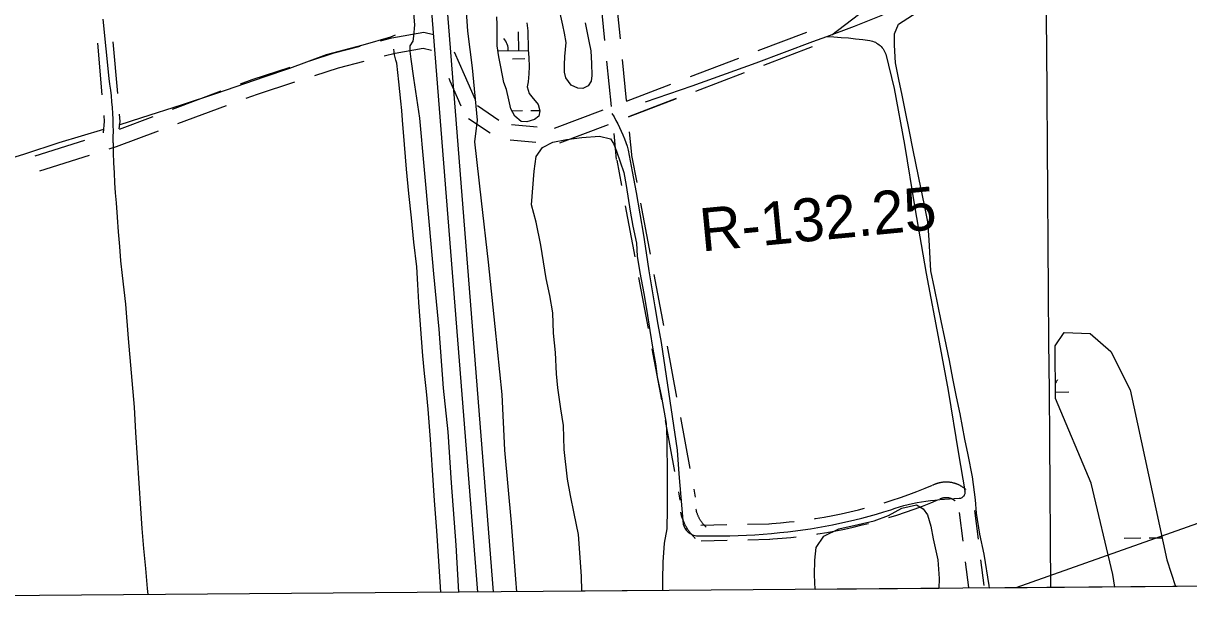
# Model space of a CAD drawing. Extents: x 3540316 to 3578335, y 553172 to 578787.
# Drawn here: x 3547815 to 3550058, y 558573 to 559700 of the extents above; entities that cross this region are included whole.
import ezdxf

# ---------------------------------------------------------------- set-up
doc = ezdxf.new("R2010")
doc.units = 0
for name, color, linetype in [('V-DTCH-CNTR', 7, 'Continuous'), ('V-GRID-FRAM', 7, 'Continuous'), ('V-GRID-MAJR', 7, 'Continuous'), ('V-LEVE-TOET', 7, 'Continuous'), ('V-RIVR-RANG-IDEN', 7, 'Continuous'), ('V-ROAD-CNTR', 7, 'Continuous'), ('V-SITE-VEGE', 7, 'Continuous'), ('V-SURV-LINE', 7, 'Continuous'), ('V-TOPO-BNDY', 7, 'Continuous'), ('V-TOPO-SHOR', 7, 'Continuous'), ('V-WETL-SWMP', 7, 'Continuous')]:
    doc.layers.add(name, color=color, linetype=linetype)

msp = doc.modelspace()

# ---------------------------------------------------------------- linework, layer by layer
at = {"layer": 'V-DTCH-CNTR'}
for points in [[(3547987.7, 559470.4), (3547988, 559481.7), (3547988.1, 559493), (3547988, 559504.3), (3547987.7, 559515.6), (3547987.2, 559526.9), (3547986.5, 559538.2), (3547985.5, 559549.5), (3547984.4, 559560.8), (3547983.1, 559572), (3547981.5, 559583.3), (3547979.8, 559594.4), (3547974.1, 559651.3), (3547968.6, 559708.2)], [(3549012.5, 559549), (3549102.4, 559580.2), (3549225.7, 559624.1), (3549334.7, 559665.2), (3549361.7, 559675.1), (3549415.1, 559694.7), (3549466.2, 559715.4), (3549485, 559724.9)], [(3549361.7, 559675.1), (3549375.5, 559674.4), (3549389.4, 559673.4), (3549403.2, 559672.2), (3549417, 559670.8), (3549430.7, 559669.2), (3549444.5, 559667.4), (3549447.2, 559666.8), (3549449.9, 559666), (3549452.6, 559665), (3549455.2, 559663.9), (3549457.6, 559662.5), (3549460, 559661), (3549462.3, 559659.3), (3549464.4, 559657.5), (3549466.4, 559655.5), (3549468.3, 559653.4), (3549470, 559651.2), (3549471.5, 559648.8), (3549472.8, 559646.3), (3549474, 559643.8), (3549475, 559641.1), (3549491.6, 559575.2), (3549511, 559467.1), (3549530.9, 559345.4), (3549552.8, 559218.8), (3549577.7, 559086.3), (3549595, 558993.4), (3549615.5, 558871.2), (3549627.7, 558800.2)], [(3548618.6, 558604.9), (3548614.8, 558664.5), (3548610.7, 558723.1), (3548606.6, 558781.7), (3548602.5, 558840.3), (3548598.4, 558898.9), (3548594.4, 558957.5), (3548590.7, 558991.7), (3548587.3, 559026), (3548584.2, 559060.2), (3548581.3, 559094.5), (3548578.6, 559128.8), (3548576.2, 559163.1), (3548574, 559197.4), (3548572.1, 559231.7), (3548566.9, 559278.8), (3548562, 559325.8), (3548557.3, 559372.8), (3548552.8, 559419.9), (3548548.6, 559467), (3548544.7, 559514.1), (3548543.3, 559532.5), (3548541.6, 559550.8), (3548539.9, 559569.2), (3548538, 559587.5), (3548536, 559605.8), (3548533.8, 559624), (3548532.2, 559629.2), (3548530.8, 559634.5), (3548529.7, 559639.9), (3548528.8, 559645.3), (3548528.1, 559650.7)], [(3548948.1, 559526.9), (3548952, 559520.2), (3548955.8, 559513.4), (3548959.4, 559506.6), (3548962.8, 559499.6), (3548966, 559492.6), (3548969.1, 559485.4), (3548971.9, 559478.2), (3548974.6, 559471), (3548977.1, 559463.6), (3548979.4, 559456.2), (3548987.2, 559415.4), (3548994.7, 559374.6), (3549001.9, 559333.7), (3549008.8, 559292.7), (3549013.9, 559258.2), (3549019.3, 559223.6), (3549024.8, 559189.1), (3549030.5, 559154.6), (3549036.4, 559120.2), (3549042.5, 559085.8), (3549073.3, 558878.3), (3549076.9, 558833.2), (3549080.7, 558788.1), (3549084.5, 558743), (3549084.6, 558740.5), (3549084.9, 558738), (3549085.4, 558735.5), (3549086.1, 558733.1), (3549087.1, 558730.8), (3549088.2, 558728.5), (3549089.6, 558726.4), (3549091.1, 558724.4), (3549092.8, 558722.5), (3549094.6, 558720.8), (3549096.6, 558719.2), (3549098.7, 558717.8), (3549100.9, 558716.6), (3549103.2, 558715.6), (3549105.6, 558714.8), (3549108.1, 558714.3), (3549110.6, 558713.9), (3549126.6, 558713.5), (3549142.7, 558713.4), (3549158.8, 558713.4), (3549174.8, 558713.7), (3549190.9, 558714.2), (3549206.9, 558714.9), (3549223, 558715.8), (3549239, 558716.9), (3549255, 558718.2), (3549271, 558719.7), (3549286.9, 558721.5), (3549301.3, 558723.2), (3549315.7, 558725.1), (3549330, 558727.3), (3549344.3, 558729.6), (3549358.6, 558732.1), (3549372.8, 558734.9), (3549387, 558737.8), (3549401.2, 558740.9), (3549415.3, 558744.3), (3549429.4, 558747.8), (3549443.4, 558751.5), (3549457.3, 558755.5), (3549471.2, 558759.6), (3549485, 558763.9), (3549493.3, 558766.7), (3549501.6, 558769.4), (3549509.9, 558771.8), (3549518.4, 558773.9), (3549526.9, 558775.9), (3549535.4, 558777.6), (3549544, 558779.1), (3549552.6, 558780.3), (3549561.3, 558781.3), (3549569.9, 558782.1), (3549579.2, 558783.3), (3549588.4, 558784.3), (3549597.7, 558785), (3549607, 558785.5), (3549616.3, 558785.8), (3549618, 558785.9), (3549619.5, 558786.3), (3549621.1, 558786.8), (3549622.5, 558787.6), (3549623.8, 558788.6), (3549625, 558789.7), (3549626, 558790.9), (3549626.8, 558792.3), (3549627.4, 558793.8), (3549627.8, 558795.4)], [(3547987.7, 559470.4), (3547988, 559451.1), (3547988.6, 559431.8), (3547989.5, 559412.6), (3547990.6, 559393.4), (3547991.9, 559374.1), (3547993.6, 559354.9), (3547995.4, 559326.9), (3547997.4, 559298.9), (3547999.7, 559271), (3548002.2, 559243), (3548005, 559215.1), (3548008.1, 559187.2), (3548011.4, 559159.4), (3548016.9, 559093.4), (3548022.4, 559027.4), (3548028, 558961.4), (3548030.7, 558912.6), (3548033.7, 558863.8), (3548036.9, 558815), (3548040.3, 558766.2), (3548043.2, 558727.6), (3548046.3, 558689), (3548049.7, 558650.4), (3548053.4, 558611.9), (3548054.5, 558600.5)], [(3549627.8, 558795.4), (3549628, 558797), (3549628, 558798.6), (3549627.7, 558800.2)]]:
    msp.add_lwpolyline(points, dxfattribs=at)
at = {"layer": 'V-GRID-FRAM'}
msp.add_lwpolyline([(3544387.2, 576756), (3576013, 576999.8), (3576161.1, 558817.2), (3544519.4, 558573.3), (3544387.2, 576756)], dxfattribs=at)
at = {"layer": 'V-GRID-MAJR'}
msp.add_spline([(3549793, 558613.9), (3549748.1, 564672.9), (3549703.1, 570733.8), (3549658.2, 576794.8), (3549658.2, 576796.7)], degree=3, dxfattribs=at)
at = {"layer": 'V-LEVE-TOET'}
for points in [[(3548689, 559513.8), (3548679.3, 559614.7), (3548670.6, 559685.6), (3548663.6, 559790.1), (3548654.6, 559906.5), (3548645.6, 560011.5), (3548639.8, 560118), (3548630.7, 560243.8), (3548621.2, 560361.3), (3548614.5, 560479.6), (3548602.8, 560594.3), (3548594.9, 560713.8), (3548584.4, 560819.2), (3548574.1, 560944.1), (3548567.4, 561062), (3548559.4, 561201.1), (3548555.6, 561289.3), (3548543.2, 561437.7), (3548530.1, 561572.4), (3548518.7, 561693.5), (3548505.7, 561814.5)], [(3548562.3, 559765.9), (3548568.2, 559697.8), (3548566, 559675.4), (3548564.5, 559666), (3548559.1, 559656.9)], [(3548559.1, 559656.9), (3548559.2, 559646.8), (3548560.9, 559631.5), (3548566.2, 559595.1), (3548577.3, 559517.6), (3548585.8, 559425.1), (3548596.4, 559311.9), (3548604.5, 559217.9), (3548614.6, 559111.4), (3548623.3, 558997.8), (3548632.1, 558914), (3548638.2, 558815.7), (3548647.3, 558695.4), (3548652.8, 558605.1)], [(3548765.1, 558606), (3548763, 558630.4), (3548754.4, 558738.9), (3548742.1, 558878.7), (3548736.6, 558985.7), (3548723.5, 559116.5), (3548710.1, 559240.2), (3548696.8, 559358.5), (3548683.8, 559472), (3548689, 559513.8)]]:
    msp.add_lwpolyline(points, dxfattribs=at)
at = {"layer": 'V-ROAD-CNTR'}
for points in [[(3548934.3, 559667.4), (3548924.5, 559766.9)], [(3548964.2, 559670.4), (3548954.4, 559769.9)], [(3549371.5, 559678.1), (3549422.8, 559717.5), (3549451.2, 559737.4)], [(3548502.2, 559666.6), (3548524.4, 559672.4), (3548585.7, 559683.2), (3548604.6, 559678.7)], [(3549229.7, 559647.8), (3549323.1, 559683.5)], [(3547966.8, 559562.6), (3547958, 559662.2)], [(3547996.7, 559565.2), (3547987.9, 559664.8)], [(3548366.6, 559628.4), (3548413.1, 559643.5), (3548463.5, 559656.6)], [(3548509.7, 559637.6), (3548530.8, 559643), (3548584.8, 559652.6), (3548600.3, 559648.9)], [(3548644, 559645.3), (3548663.6, 559602), (3548684.7, 559553.8)], [(3549240.4, 559619.8), (3549333.8, 559655.5)], [(3548233.2, 559584.1), (3548255.5, 559592.4), (3548328.6, 559616.1)], [(3548375.9, 559599.9), (3548421.5, 559614.7), (3548471, 559627.5)], [(3548946.9, 559540), (3548938.3, 559627.6)], [(3548975.9, 559551.6), (3548968.1, 559630.5)], [(3549099, 559597.8), (3549192.4, 559633.5)], [(3548633.9, 559594.8), (3548636.2, 559589.8), (3548657.2, 559541.7)], [(3549109.7, 559569.8), (3549203.1, 559605.5)], [(3548243.6, 559556), (3548265.4, 559564.1), (3548337.8, 559587.6)], [(3548976.2, 559550.8), (3549061.6, 559583.5)], [(3548102, 559535.3), (3548195.7, 559570.1)], [(3548980, 559520.1), (3549072.3, 559555.5)], [(3548980.8, 559521), (3549072.1, 559556)], [(3548112.4, 559507.2), (3548206.1, 559542)], [(3548689, 559542.2), (3548730.3, 559514.1)], [(3548837.3, 559498.3), (3548930.9, 559533.6)], [(3547969, 559489.7), (3547971.4, 559511.3), (3547970.3, 559522.7)], [(3547999.1, 559497.2), (3548001.5, 559511.1), (3548000.2, 559525.4)], [(3548000.2, 559497.2), (3548000.2, 559496.6), (3548064.5, 559521.3)], [(3548672.1, 559517.4), (3548713.4, 559489.3)], [(3548754.5, 559505.8), (3548804.3, 559501.4)], [(3548847.9, 559470.2), (3548941.5, 559505.5)], [(3547980.3, 559458.8), (3547994.1, 559463.2), (3548074.9, 559493.2)], [(3548956.9, 559438.5), (3548952, 559488.3)], [(3548986.8, 559441.5), (3548981.9, 559491.2)], [(3547837.7, 559445.2), (3547933.1, 559475.3)], [(3548751.8, 559475.9), (3548801.6, 559471.5)], [(3547846.8, 559416.6), (3547942.1, 559446.7)], [(3548957.1, 559437.2), (3548966.3, 559388.1)], [(3548986.6, 559442.7), (3548995.7, 559393.6)], [(3548973.6, 559348.8), (3548991.9, 559250.5)], [(3549003.1, 559354.3), (3549021.4, 559255.9)], [(3549028.7, 559216.6), (3549047, 559118.3)], [(3548999.2, 559211.1), (3549017.5, 559112.8)], [(3549054.3, 559079), (3549072.6, 558980.7)], [(3549024.8, 559073.5), (3549043.1, 558975.2)], [(3549050.4, 558935.9), (3549068.7, 558837.6)], [(3549079.9, 558941.4), (3549098.2, 558843)], [(3549472.3, 558777.4), (3549487.4, 558782.1), (3549503.4, 558787.4), (3549519.3, 558793.1), (3549535.2, 558799), (3549550.8, 558805.1), (3549564.9, 558811)], [(3549565.5, 558811.2), (3549565.5, 558811.2), (3549566.1, 558811.5), (3549567, 558811.9), (3549567.9, 558812.4), (3549568.8, 558812.8), (3549569.7, 558813.1), (3549570.6, 558813.5), (3549571.5, 558813.9), (3549572.4, 558814.2), (3549573.3, 558814.5), (3549574.2, 558814.9), (3549575.1, 558815.1), (3549576.1, 558815.4), (3549577, 558815.7), (3549578, 558815.9), (3549578.9, 558816.2), (3549579.8, 558816.4), (3549580.8, 558816.5), (3549581.8, 558816.7), (3549582.7, 558816.9), (3549583.6, 558817), (3549584.6, 558817.2), (3549585.6, 558817.3), (3549586.6, 558817.4), (3549587.5, 558817.4), (3549588.5, 558817.5), (3549589.5, 558817.5), (3549590.4, 558817.6), (3549591.3, 558817.6), (3549592.4, 558817.6), (3549593.3, 558817.5), (3549594.3, 558817.5), (3549595.3, 558817.4), (3549596.2, 558817.4), (3549597.2, 558817.3), (3549598.2, 558817.2), (3549599.1, 558817), (3549600.1, 558816.9), (3549601.1, 558816.7), (3549602, 558816.6), (3549603, 558816.4), (3549603.9, 558816.2), (3549604.8, 558815.9), (3549605.8, 558815.7), (3549606.7, 558815.4), (3549607.6, 558815.2), (3549608.5, 558814.9), (3549609.5, 558814.6), (3549610.4, 558814.2), (3549611.3, 558813.9), (3549612.2, 558813.5), (3549613.1, 558813.2), (3549614, 558812.8), (3549614.9, 558812.4), (3549615.8, 558812), (3549616.6, 558811.5), (3549617.5, 558811.1), (3549618.3, 558810.6), (3549619.2, 558810.1), (3549620, 558809.6), (3549620.8, 558809.1), (3549621.6, 558808.6), (3549622.5, 558808.1), (3549623.3, 558807.5), (3549624, 558807), (3549624.8, 558806.4), (3549625.6, 558805.8), (3549626.4, 558805.2), (3549627.1, 558804.6), (3549627.9, 558803.9), (3549628.6, 558803.3), (3549628.9, 558803)], [(3549076.1, 558798.2), (3549079, 558782.5)], [(3549105.6, 558803.7), (3549108.5, 558788)], [(3549579.1, 558784.4), (3549579.2, 558784.5), (3549579.8, 558784.8), (3549580.2, 558785), (3549580.6, 558785.2), (3549581, 558785.4), (3549581.4, 558785.5), (3549581.8, 558785.7), (3549582.2, 558785.9), (3549582.7, 558786), (3549583.1, 558786.2), (3549583.5, 558786.3), (3549583.9, 558786.5), (3549584.4, 558786.6), (3549584.8, 558786.7), (3549585.2, 558786.8), (3549585.6, 558786.9), (3549586.1, 558787), (3549586.5, 558787.1), (3549586.9, 558787.2), (3549587.4, 558787.3), (3549587.9, 558787.3), (3549588.3, 558787.4), (3549588.7, 558787.4), (3549589.1, 558787.5), (3549589.6, 558787.5), (3549590.1, 558787.5), (3549590.5, 558787.6), (3549590.9, 558787.6), (3549591.4, 558787.6), (3549591.8, 558787.6), (3549592.3, 558787.6), (3549592.7, 558787.5), (3549593.1, 558787.5), (3549593.6, 558787.5), (3549594.1, 558787.4), (3549594.5, 558787.4), (3549595, 558787.3), (3549595.4, 558787.3), (3549595.8, 558787.2), (3549596.3, 558787.1), (3549596.7, 558787), (3549597.2, 558786.9), (3549597.6, 558786.8), (3549598, 558786.7), (3549598.4, 558786.6), (3549598.9, 558786.5), (3549599.3, 558786.3), (3549599.7, 558786.2), (3549600.1, 558786), (3549600.6, 558785.9), (3549601, 558785.7), (3549601.4, 558785.5), (3549601.8, 558785.4), (3549602.2, 558785.2), (3549602.6, 558785), (3549603, 558784.8), (3549603.4, 558784.6), (3549603.8, 558784.4), (3549604.2, 558784.2), (3549604.5, 558783.9), (3549605, 558783.7), (3549605.3, 558783.4), (3549605.7, 558783.2), (3549606, 558783), (3549606.4, 558782.7), (3549606.8, 558782.4), (3549607.1, 558782.2), (3549607.5, 558781.9), (3549607.9, 558781.6), (3549608.2, 558781.3), (3549608.5, 558781), (3549608.7, 558780.8)], [(3549129.6, 558730.1), (3549128.7, 558730.9), (3549127.9, 558731.7), (3549127, 558732.6), (3549126.2, 558733.4), (3549125.5, 558734.2), (3549124.7, 558735.1), (3549123.9, 558736), (3549123.2, 558736.8), (3549122.5, 558737.7), (3549121.8, 558738.6), (3549121.1, 558739.6), (3549120.4, 558740.5), (3549119.8, 558741.4), (3549119.2, 558742.4), (3549118.5, 558743.4), (3549117.9, 558744.3), (3549117.4, 558745.3), (3549116.8, 558746.3), (3549116.2, 558747.3), (3549115.7, 558748.3), (3549115.2, 558749.4), (3549114.7, 558750.4), (3549114.2, 558751.4), (3549113.8, 558752.5), (3549113.3, 558753.5), (3549112.9, 558754.6), (3549112.5, 558755.7), (3549112.1, 558756.7), (3549111.7, 558757.8), (3549111.4, 558758.9), (3549111, 558760.1), (3549110.7, 558761.1), (3549110.5, 558762.2), (3549110.2, 558763.4), (3549109.9, 558764.5), (3549109.8, 558765)], [(3549338.2, 558746.6), (3549339.8, 558746.9), (3549356.4, 558749.6), (3549373, 558752.6), (3549389.6, 558756.1), (3549406, 558759.7), (3549422.5, 558763.6), (3549434.5, 558766.7)], [(3549481.2, 558748.8), (3549496.6, 558753.6), (3549513.1, 558759.1), (3549529.6, 558764.9), (3549545.8, 558771), (3549562, 558777.3), (3549576.5, 558783.3)], [(3549109.1, 558708.2), (3549107.9, 558709.3), (3549106.7, 558710.5), (3549105.6, 558711.6), (3549104.4, 558712.8), (3549103.2, 558714.1), (3549102.2, 558715.3), (3549101.1, 558716.6), (3549100, 558717.9), (3549098.9, 558719.2), (3549097.9, 558720.5), (3549096.9, 558721.8), (3549096, 558723.2), (3549095, 558724.6), (3549094.1, 558726), (3549093.2, 558727.3), (3549092.3, 558728.8), (3549091.4, 558730.2), (3549090.6, 558731.7), (3549089.8, 558733.1), (3549089, 558734.6), (3549088.3, 558736.1), (3549087.5, 558737.6), (3549086.9, 558739.1), (3549086.2, 558740.7), (3549085.5, 558742.2), (3549084.9, 558743.7), (3549084.3, 558745.3), (3549083.8, 558746.9), (3549083.2, 558748.5), (3549082.7, 558750), (3549082.2, 558751.6), (3549081.8, 558753.3), (3549081.4, 558754.9), (3549081, 558756.5), (3549080.6, 558758.1), (3549080.4, 558759)], [(3549250, 558737), (3549255.9, 558737.4), (3549272.8, 558738.7), (3549289.5, 558740.3), (3549299.1, 558741.4)], [(3549623.9, 558703.5), (3549617.1, 558758.8)], [(3549653.6, 558707.2), (3549646.8, 558762.4)], [(3549119, 558734.1), (3549169, 558735.2)], [(3549209, 558736.1), (3549250.6, 558737)], [(3549342.6, 558717), (3549344.4, 558717.2), (3549361.6, 558720), (3549378.8, 558723.2), (3549395.8, 558726.7), (3549412.7, 558730.4), (3549429.7, 558734.5), (3549442, 558737.6)], [(3549119.7, 558704.1), (3549169.6, 558705.2)], [(3549209.6, 558706.1), (3549251.3, 558707)], [(3549252, 558707.1), (3549258, 558707.5), (3549275.4, 558708.8), (3549292.7, 558710.5), (3549302.4, 558711.6)], [(3549634.9, 558614.2), (3549628.8, 558663.8)], [(3549664.6, 558617.9), (3549658.5, 558667.5)]]:
    msp.add_lwpolyline(points, dxfattribs=at)
at = {"layer": 'V-SITE-VEGE'}
for p, q in [((3549499.8, 559699), (3549544.7, 559727.7)), ((3549492.2, 559680.1), (3549499.8, 559699)), ((3549491.9, 559658.6), (3549492.2, 559680.1)), ((3549493.7, 559624.1), (3549491.9, 559658.6)), ((3549500.2, 559592.1), (3549493.7, 559624.1)), ((3549506.7, 559562), (3549500.2, 559592.1)), ((3549514, 559526.9), (3549506.7, 559562)), ((3549520.4, 559495.2), (3549514, 559526.9)), ((3548890.3, 559480.3), (3548923.9, 559482.9)), ((3548923.9, 559482.9), (3548945.1, 559477.9)), ((3549528.1, 559456.2), (3549520.4, 559495.2)), ((3548802.2, 559443.7), (3548814.2, 559461.4)), ((3548814.2, 559461.4), (3548834, 559471.3)), ((3548834, 559471.3), (3548860.6, 559476.6)), ((3548860.6, 559476.6), (3548890.3, 559480.3)), ((3548945.1, 559477.9), (3548951, 559469)), ((3548951, 559469), (3548957, 559454.5)), ((3548798.4, 559415.9), (3548802.2, 559443.7)), ((3548957, 559454.5), (3548971, 559413.2)), ((3549543.5, 559381.1), (3549528.1, 559456.2)), ((3548793, 559350.9), (3548798.4, 559415.9)), ((3548971, 559413.2), (3548975.1, 559388.2)), ((3548975.1, 559388.2), (3548982.8, 559338.5)), ((3549549.2, 559353.4), (3549543.5, 559381.1)), ((3548801.9, 559317.3), (3548793, 559350.9)), ((3549556.1, 559318.3), (3549549.2, 559353.4)), ((3548982.8, 559338.5), (3548988.5, 559310)), ((3548811.2, 559273.2), (3548801.9, 559317.3)), ((3548988.5, 559310), (3548995.4, 559277.2)), ((3549558.7, 559283.8), (3549556.1, 559318.3)), ((3549562.2, 559223.6), (3549558.7, 559283.8)), ((3548821.4, 559209.1), (3548811.2, 559273.2)), ((3548995.4, 559277.2), (3548996.7, 559251.8)), ((3548996.7, 559251.8), (3549001.6, 559220.9)), ((3549001.6, 559220.9), (3549009.4, 559180.3)), ((3549569.1, 559190.4), (3549562.2, 559223.6)), ((3548828.7, 559176.3), (3548821.4, 559209.1)), ((3549576, 559155.6), (3549569.1, 559190.4)), ((3548834.4, 559143.1), (3548828.7, 559176.3)), ((3549009.4, 559180.3), (3549015.1, 559145.9)), ((3549015.1, 559145.9), (3549020.8, 559109.2)), ((3549582.1, 559127.5), (3549576, 559155.6)), ((3548835.8, 559104), (3548834.4, 559143.1)), ((3549588.9, 559094.3), (3549582.1, 559127.5)), ((3548839.6, 559066.8), (3548835.8, 559104)), ((3549020.8, 559109.2), (3549026.5, 559073.2)), ((3549597.9, 559051), (3549588.9, 559094.3)), ((3548841.4, 559025.4), (3548839.6, 559066.8)), ((3549026.5, 559073.2), (3549031.8, 559044.7)), ((3549031.8, 559044.7), (3549035.1, 559019.7)), ((3549604.4, 559016.2), (3549597.9, 559051)), ((3548844, 558998.4), (3548841.4, 559025.4)), ((3549035.1, 559019.7), (3549043.2, 558980.6)), ((3549611.2, 558981), (3549604.4, 559016.2)), ((3548849.7, 558958.1), (3548844, 558998.4)), ((3549043.2, 558980.6), (3549052.2, 558929.8)), ((3549618.1, 558948.2), (3549611.2, 558981)), ((3548855, 558926.1), (3548849.7, 558958.1)), ((3549627.1, 558899.4), (3549618.1, 558948.2)), ((3548856.1, 558879.5), (3548855, 558926.1)), ((3549052.2, 558929.8), (3549053.9, 558900.5)), ((3549053.9, 558900.5), (3549054.5, 558827.3)), ((3549633.9, 558869.3), (3549627.1, 558899.4)), ((3548862.4, 558822.9), (3548856.1, 558879.5)), ((3549642, 558827.1), (3549633.9, 558869.3)), ((3548868.1, 558791.2), (3548862.4, 558822.9)), ((3549054.5, 558827.3), (3549054.3, 558798.4)), ((3549648.2, 558782.9), (3549642, 558827.1)), ((3548875.4, 558756.8), (3548868.1, 558791.2)), ((3549054.3, 558798.4), (3549054.5, 558764.7)), ((3549054.5, 558764.7), (3549053.6, 558727.2)), ((3549480.2, 558752.8), (3549505.9, 558767.1)), ((3549505.9, 558767.1), (3549534.5, 558773.2)), ((3549534.5, 558773.2), (3549547.4, 558765.8)), ((3549547.4, 558765.8), (3549555.3, 558754.1)), ((3549649.6, 558757.1), (3549648.2, 558782.9)), ((3548883.9, 558716.2), (3548875.4, 558756.8)), ((3549422, 558735.2), (3549452.9, 558742.5)), ((3549452.9, 558742.5), (3549480.2, 558752.8)), ((3549555.3, 558754.1), (3549561.7, 558731.9)), ((3549656.1, 558716.5), (3549649.6, 558757.1)), ((3549053.6, 558727.2), (3549048.7, 558699.4)), ((3549355.7, 558713.2), (3549384.9, 558727.1)), ((3549384.9, 558727.1), (3549422, 558735.2)), ((3549561.7, 558731.9), (3549566.6, 558708)), ((3548889.1, 558636.1), (3548883.9, 558716.2)), ((3549048.7, 558699.4), (3549045.8, 558662.6)), ((3549341, 558690.8), (3549355.7, 558713.2)), ((3549566.6, 558708), (3549575.1, 558667.4)), ((3549664.6, 558678.6), (3549656.1, 558716.5)), ((3549338.4, 558666.6), (3549341, 558690.8)), ((3549674.4, 558618), (3549664.6, 558678.6)), ((3549045.8, 558662.6), (3549045.3, 558628.9)), ((3549338.2, 558638.4), (3549338.4, 558666.6)), ((3549575.1, 558667.4), (3549577.7, 558631.4)), ((3548889.9, 558607), (3548889.1, 558636.1)), ((3549045.3, 558628.9), (3549045.4, 558608.2)), ((3549339.1, 558610.4), (3549338.2, 558638.4)), ((3549577.7, 558631.4), (3549577.3, 558612.3)), ((3549045.4, 558608.2), (3548889.9, 558607)), ((3549577.3, 558612.3), (3549339.1, 558610.4)), ((3549674.8, 558613), (3549674.4, 558618)), ((3550579.6, 558620), (3549674.8, 558613))]:
    msp.add_line(p, q, dxfattribs=at)
at = {"layer": 'V-SURV-LINE'}
for points in [[(3548689.6, 558605.4), (3548371.1, 562630.7)], [(3548401, 562633.1), (3548719.6, 558605.7)]]:
    msp.add_lwpolyline(points, dxfattribs=at)
at = {"layer": 'V-TOPO-BNDY'}
msp.add_lwpolyline([(3550561, 558909.1), (3549725.6, 558613.4)], dxfattribs=at)
at = {"layer": 'V-TOPO-SHOR'}
for points in [[(3548530.8, 559677.9), (3548521.4, 559673.7), (3548468.7, 559658.5), (3548397.6, 559639.6), (3548327.4, 559613.3), (3548277.8, 559596.5), (3548186.5, 559565.3), (3548118.6, 559543), (3548042.4, 559518.6), (3547998.7, 559504.2)], [(3547969.4, 559496.2), (3547883.2, 559470.5), (3547817.2, 559448.6), (3547714.9, 559416.9)]]:
    msp.add_lwpolyline(points, dxfattribs=at)
at = {"layer": 'V-WETL-SWMP'}
for p, q in [((3548768.5, 559647.8), (3548768.2, 559683.8)), ((3548728.4, 559647.5), (3548787.2, 559647.9)), ((3548756.6, 559632.2), (3548780.6, 559632.4)), ((3548755.2, 559532.2), (3548776, 559532.4)), ((3548792, 559532.5), (3548809.1, 559532.6)), ((3549801.5, 559079.6), (3549818.7, 559105.2)), ((3549818.7, 559105.2), (3549868.6, 559103.2)), ((3549868.6, 559103.2), (3549908.2, 559068.8)), ((3549802.2, 558977.7), (3549801.5, 559079.6)), ((3549908.2, 559068.8), (3549945.7, 558994.9)), ((3549802.1, 558990.4), (3549827.4, 558990.6)), ((3549945.7, 558994.9), (3550016.3, 558667.5)), ((3549870.5, 558814.8), (3549802.2, 558977.7)), ((3549912.2, 558639), (3549870.5, 558814.8)), ((3549934.2, 558709.4), (3549966.2, 558709.7)), ((3549982.2, 558709.8), (3550007.1, 558710)), ((3550016.3, 558667.5), (3550033, 558615.8)), ((3549916.1, 558614.9), (3549912.2, 558639)), ((3550033, 558615.8), (3549916.1, 558614.9))]:
    msp.add_line(p, q, dxfattribs=at)
for points in [[(3548783.9, 559701.5), (3548785.9, 559685.8), (3548787, 559650.3), (3548788.3, 559633.8), (3548788.4, 559617), (3548788.1, 559602.9), (3548787, 559587.7), (3548785.1, 559577.9), (3548788.4, 559565.4), (3548793.9, 559558.8), (3548805.7, 559544), (3548809.3, 559531.9), (3548807, 559521.7), (3548798.9, 559515), (3548784, 559511), (3548773.1, 559511.3), (3548760.9, 559521.4), (3548753.3, 559535.8), (3548749.7, 559553.4), (3548745.3, 559572.9), (3548740.1, 559586.6), (3548734, 559616.6), (3548730, 559636.2), (3548727.1, 559656.9), (3548726.9, 559680), (3548726.8, 559698.3), (3548726.7, 559712.8)], [(3548896.6, 559701.5), (3548900.6, 559682.3), (3548903.5, 559665.9), (3548907.1, 559647.2), (3548908.8, 559623.3), (3548909, 559600.2), (3548907.9, 559588.9), (3548902.1, 559580.2), (3548892, 559575.1), (3548882.6, 559575.8), (3548869.2, 559581.6), (3548859, 559595.6), (3548856.9, 559606.1), (3548856.8, 559620.6), (3548857.5, 559636.3), (3548860, 559663.7), (3548856.4, 559681.3), (3548853.2, 559696.9), (3548848.3, 559719.9)]]:
    msp.add_lwpolyline(points, dxfattribs=at)
for centre, start, end in [((3548713.3, 559647.8), 359.6699, 41.2135), ((3549832.7, 558991.1), 139.6699, 150.4242)]:
    msp.add_arc(centre, 35.2, start, end, dxfattribs=at)

# ---------------------------------------------------------------- texts
at = {"layer": 'V-RIVR-RANG-IDEN'}
msp.add_text('R-132.25', height=83, rotation=5.4691, dxfattribs=at).set_placement((3549121, 559260.9))

doc.saveas('drawing.dxf')
